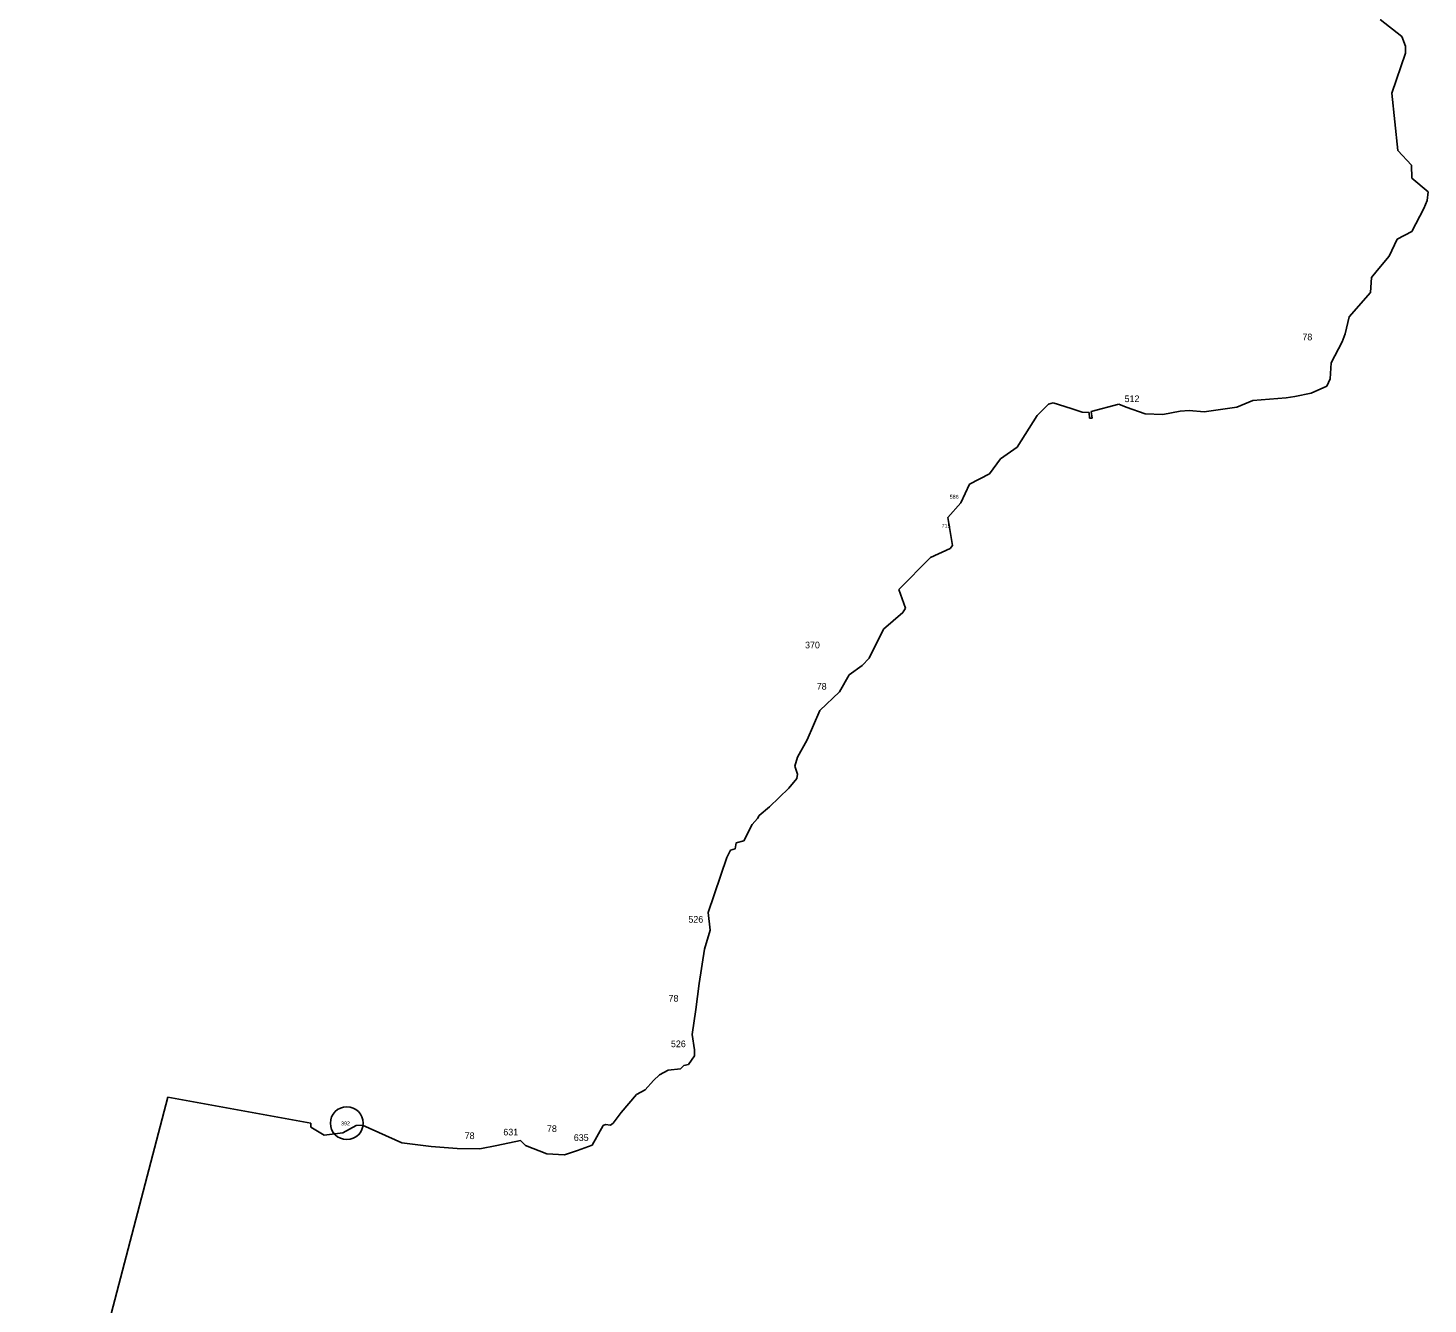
# Model space of a CAD drawing. Extents: x -782977 to -778030, y -975420 to -964838.
# Drawn here: x -779792 to -778338, y -968811 to -967487 of the extents above; entities that cross this region are included whole.
import ezdxf

# ---------------------------------------------------------------- set-up
doc = ezdxf.new("R2010")
doc.units = 0
doc.layers.add('Vrstva 13', color=7, linetype='Continuous')
doc.layers.add('Vrstva 24', color=7, linetype='Continuous')

msp = doc.modelspace()

# ---------------------------------------------------------------- linework, layer by layer
at = {"layer": 'Vrstva 13'}
for p, q in [((-778365.53, -967495.83), (-778388.18, -967478.07)), ((-778361.66, -967505.76), (-778365.53, -967495.83)), ((-778361.59, -967512.92), (-778361.66, -967505.76)), ((-778376.05, -967554.49), (-778361.59, -967512.92)), ((-778369.77, -967614.19), (-778376.05, -967554.49)), ((-778355.6, -967629.24), (-778369.77, -967614.19)), ((-778355.02, -967642.84), (-778355.6, -967629.24)), ((-778338.36, -967657.01), (-778355.02, -967642.84)), ((-778342.75, -967674.25), (-778339.39, -967665.92)), ((-778339.39, -967665.92), (-778338.36, -967657.01)), ((-778355.16, -967698.22), (-778342.75, -967674.25)), ((-778378.53, -967723.65), (-778370.35, -967706.26)), ((-778370.35, -967706.26), (-778355.16, -967698.22)), ((-778391.24, -967738.7), (-778378.53, -967723.65)), ((-778396.93, -967745.85), (-778391.24, -967738.7)), ((-778397.95, -967761.53), (-778396.93, -967745.85)), ((-778420.13, -967786.78), (-778397.95, -967761.53)), ((-778424.2, -967804.29), (-778420.13, -967786.78)), ((-778439.01, -967834.38), (-778427.61, -967812.7)), ((-778427.61, -967812.7), (-778424.2, -967804.29)), ((-778440.09, -967851.04), (-778439.01, -967834.38)), ((-778440.09, -967851.04), (-778443.45, -967858.87)), ((-778485.77, -967870.78), (-778520.37, -967873.53)), ((-778476.52, -967869.46), (-778485.77, -967870.78)), ((-778459.62, -967866), (-778476.52, -967869.46)), ((-778443.45, -967858.87), (-778459.62, -967866)), ((-778732.25, -967877.56), (-778744.05, -967889.17)), ((-778727.57, -967876.14), (-778732.25, -967877.56)), ((-778708.72, -967882.02), (-778727.57, -967876.14)), ((-778697.58, -967885.73), (-778708.72, -967882.02)), ((-778690.1, -967886.04), (-778697.58, -967885.73)), ((-778689.7, -967892.04), (-778690.1, -967886.04)), ((-778659.45, -967877.41), (-778688.04, -967885.05)), ((-778688.04, -967885.05), (-778687.2, -967892.09)), ((-778651.92, -967880.37), (-778659.45, -967877.41)), ((-778631.98, -967887.29), (-778651.92, -967880.37)), ((-778595.55, -967884.54), (-778613.77, -967888.2)), ((-778586.45, -967883.98), (-778595.55, -967884.54)), ((-778570.63, -967885.34), (-778586.45, -967883.98)), ((-778536.95, -967880.55), (-778570.63, -967885.34)), ((-778520.37, -967873.53), (-778536.95, -967880.55)), ((-778744.05, -967889.17), (-778764.81, -967921.94)), ((-778687.2, -967892.09), (-778689.7, -967892.04)), ((-778613.77, -967888.2), (-778631.98, -967887.29)), ((-778764.81, -967921.94), (-778782.16, -967934.11)), ((-778782.16, -967934.11), (-778793.66, -967949.88)), ((-778793.66, -967949.88), (-778814.32, -967960.47)), ((-778814.32, -967960.47), (-778823.37, -967979.71)), ((-778823.37, -967979.71), (-778836.91, -967995.18)), ((-778836.91, -967995.18), (-778831.93, -968024.19)), ((-778834.57, -968027.14), (-778854.93, -968036.6)), ((-778831.93, -968024.19), (-778834.57, -968027.14)), ((-778854.93, -968036.6), (-778887.74, -968069.94)), ((-778887.74, -968069.94), (-778881.02, -968089.08)), ((-778881.02, -968089.08), (-778883.47, -968093.76)), ((-778883.47, -968093.76), (-778903.87, -968110.91)), ((-778903.87, -968110.91), (-778918.72, -968140.94)), ((-778918.72, -968140.94), (-778925.85, -968148.78)), ((-778939.48, -968158.35), (-778949.35, -968176.06)), ((-778925.85, -968148.78), (-778939.48, -968158.35)), ((-778949.35, -968176.06), (-778969.91, -968195.5)), ((-778969.91, -968195.5), (-778983.04, -968225.94)), ((-778983.04, -968225.94), (-778993.11, -968243.75)), ((-778993.11, -968243.75), (-778995.78, -968252.99)), ((-778995.78, -968252.99), (-778993.08, -968261.34)), ((-778993.08, -968261.34), (-778993.69, -968265.82)), ((-779002.01, -968276.07), (-779022.06, -968295.21)), ((-778993.69, -968265.82), (-779002.01, -968276.07)), ((-779040.1, -968313.84), (-779034.4, -968307.43)), ((-779034.4, -968307.43), (-779032.77, -968304.37)), ((-779032.77, -968304.37), (-779022.06, -968295.21)), ((-779048.86, -968330.54), (-779040.1, -968313.84)), ((-779057.71, -968338.99), (-779056.59, -968332.78)), ((-779056.59, -968332.78), (-779048.86, -968330.54)), ((-779085.74, -968404.92), (-779066.41, -968347.9)), ((-779066.41, -968347.9), (-779062.49, -968340.31)), ((-779062.49, -968340.31), (-779057.71, -968338.99)), ((-779083.71, -968423.25), (-779085.74, -968404.92)), ((-779089.61, -968443.2), (-779083.71, -968423.25)), ((-779095.06, -968478.88), (-779089.61, -968443.2)), ((-779098.62, -968505.66), (-779095.06, -968478.88)), ((-779102.49, -968531.73), (-779098.62, -968505.66)), ((-779102.49, -968531.73), (-779099.869, -968547.742)), ((-779106.15, -968562.95), (-779100.07, -968553.75)), ((-779099.869, -968547.742), (-779100.07, -968553.75)), ((-779136.39, -968573.46), (-779127.23, -968568.68)), ((-779127.23, -968568.68), (-779114.61, -968567.45)), ((-779114.61, -968567.45), (-779111.05, -968563.69)), ((-779111.05, -968563.69), (-779106.15, -968562.95)), ((-779142.39, -968579.27), (-779151.14, -968589.04)), ((-779142.39, -968579.27), (-779136.39, -968573.46)), ((-779791.97, -969150.83), (-779646.87, -968596.69)), ((-779646.87, -968596.69), (-779498.41, -968623.76)), ((-779160.1, -968593.93), (-779176.1, -968612.64)), ((-779151.14, -968589.04), (-779160.1, -968593.93)), ((-779176.1, -968612.64), (-779184.39, -968623.69)), ((-779498.41, -968623.76), (-779498.41, -968627.73)), ((-779465.04, -968633.84), (-779451.4, -968626.1)), ((-779451.4, -968626.1), (-779444.69, -968625.9)), ((-779444.69, -968625.9), (-779403.78, -968644.13)), ((-779194.82, -968626.03), (-779206.21, -968646.59)), ((-779192.28, -968625.21), (-779194.82, -968626.03)), ((-779187.14, -968625.62), (-779192.28, -968625.21)), ((-779184.39, -968623.69), (-779187.14, -968625.62)), ((-779498.41, -968627.73), (-779484.37, -968636.08)), ((-779484.37, -968636.08), (-779465.04, -968633.84)), ((-779305.22, -968646.91), (-779280.67, -968641.76)), ((-779280.67, -968641.76), (-779275.43, -968647.01)), ((-779403.78, -968644.13), (-779373.47, -968647.79)), ((-779373.47, -968647.79), (-779346.5, -968649.93)), ((-779346.5, -968649.93), (-779322.87, -968650.37)), ((-779322.87, -968650.37), (-779305.22, -968646.91)), ((-779275.43, -968647.01), (-779253.3, -968655.46)), ((-779253.3, -968655.46), (-779235.08, -968656.52)), ((-779221.34, -968652.1), (-779235.08, -968656.52)), ((-779206.21, -968646.59), (-779221.34, -968652.1))]:
    msp.add_line(p, q, dxfattribs=at)
msp.add_circle((-779460.99, -968623.73), 17.023, dxfattribs=at)

# ---------------------------------------------------------------- texts
at = {"layer": 'Vrstva 24'}
for s, height, p in [('78', 6.912, (-778468.783, -967811.092)), ('512', 6.912, (-778653.395, -967875.272)), ('586', 4, (-778834.944, -967975.5)), ('715', 4, (-778843.358, -968005.7)), ('370', 6.912, (-778985.171, -968130.862)), ('78', 6.912, (-778973.043, -968173.822)), ('526', 6.912, (-779106.309, -968415.602)), ('78', 6.912, (-779126.873, -968497.532)), ('526', 6.912, (-779124.429, -968544.832)), ('392', 4, (-779466.944, -968625.93)), ('78', 6.912, (-779253.173, -968632.882)), ('78', 6.912, (-779338.583, -968640.242)), ('631', 6.912, (-779298.421, -968636.442)), ('635', 6.912, (-779225.269, -968642.132))]:
    msp.add_text(s, height=height, dxfattribs=at).set_placement(p)

doc.saveas('drawing.dxf')
